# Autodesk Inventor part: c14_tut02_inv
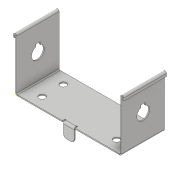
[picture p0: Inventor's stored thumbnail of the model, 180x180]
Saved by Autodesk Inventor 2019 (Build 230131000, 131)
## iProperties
Created: 2015-06
Part Number: c14_tut02_inv
Material: Generic
Document SubType Name: Sheet Metal
Designer: Sandeep
Density: 1 g/cm^3
Sheet Metal Rule: Default_mm
Appearance: Default
Flat Pattern Width: 5.12619 cm
Flat Pattern Length: 20.443 cm
Flat Pattern Area: 104.795 cm^2
Sheet Metal Width: 51.262 mm
Sheet Metal Length: 204.430 mm
Sheet Metal Area: 10479.484 mm^2
Author: Sandeep
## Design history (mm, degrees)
sketch "Sketch1"
  geometry: 1 further point
node "Face1"
  sketch "Sketch2"
    geometry: L1 (0, 0)-(100, 0); L2 (100, 0)-(100, 40); L3 (100, 40)-(0, 40); L4 (0, 40)-(0, 0)
    constraints: 8 end point, 2 parallel, 1 horizontal, 1 perpendicular
    dimensions: "d0" = 100 distance between parallel lines of L2 L4; "d1" = 40 distance between parallel lines of L1 L3
hole "Hole1" diameter "d5" = 6; stored, may be unused: countersink angle "d9" = 90 deg, drill point angle "d11" = 118 deg; dims "d3" = 10, "d4" = 15, "d6" = 6, "d7" = 4, "d8" = 2, "d10" = 1 (= Thickness)
pattern_linear "Rectangular Pattern1" dims "d14" = 20
pattern_linear "Rectangular Pattern2" dims "d17" = 70
node "Flange1"
node "Flange2"
feature "Hem1" dims "d38" = 1 (= BendReliefWidth), "d39" = 0.5 (= BendReliefDepth), "d40" = 2 (= MinimumRemnant), "d41" = 1 (= BendRadius), "d42" = 4 (= 4 x Thickness), "d43" = 1 (= Thickness), "d44" = 0.5 (= 0.5 x d43), "d82" = 1 (= Thickness), "SeamGap" = 0.01
feature "Hem2" dims "d45" = 1 (= BendReliefWidth), "d46" = 0.5 (= BendReliefDepth), "d47" = 2 (= MinimumRemnant), "d48" = 1 (= BendRadius), "d49" = 4 (= 4 x Thickness), "d50" = 1 (= Thickness), "d51" = 0.5 (= 0.5 x d50), "d82" = 1 (= Thickness), "SeamGap" = 0.01
sketch "Sketch7"
  geometry: L1 (0, 40)-(0, 0) reference; L2 (48, 0)-(0, 0) reference; 2 further points
  dimensions: "d52" = 25 distance from line of point (25, 20) L1; "d53" = 20 distance from line of L2 point (25, 20)
feature "iFeature15:1" sketch "Sketch7"
sketch "Sketch8"
  geometry: L1 (17.2, 18)-(17.2, 22) reference; L2 (19.343, 18)-(17.2, 18) reference; L3 (17.2, 22)-(19.343, 22) reference; L4 (17.2, 18)-(17.2, 22) reference; L5 (17.2, 22)-(19.343, 22) reference; L6 (19.343, 18)-(17.2, 18) reference; L7 (48, 0)-(48, 40) reference; L8 (48, 40)-(1.5, 40) reference; L9 (48, 0)-(1.5, 0) reference; L10 (1.5, 40)-(1.5, 0) reference; A1 r 6 centre (25, 20) between (19.343, 18) and (19.343, 22) reference; A2 r 6 centre (25, 20) between (19.343, 18) and (19.343, 22) reference; 1 further point
  node "Projected Loop1"
node "Flange3"
feature "Corner Round1" dims "d78" = 3
workplane "Work Plane1"
mirror "Mirror1"
body "Solid1"
face "Plate1" dims "d82" = 1 (= Thickness)
sketch "Sketch3"
  geometry: L1 through (20, 0) direction (-1, 0); L2 through (0, -25) direction (0, -1); L3 (0, -50)-(40, -50); L4 (40, -50)-(40, 0)
  constraints: 6 end point, 1 horizontal, 1 perpendicular, 1 vertical
face "Plate2" dims "d18" = 1 (= BendReliefWidth), "d19" = 0.5 (= BendReliefDepth), "d20" = 2 (= MinimumRemnant), "d21" = 1 (= BendRadius), "d22" = 50, "d23" = 90 deg, "d24" = 1 (= BendRadius), "d25" = 4 (= CornerReliefSize), "d26" = 1 (= GapSize), "d27" = 1 (= JacobiRadiusSize), "d82" = 1 (= Thickness), "SeamGap" = 0.01
bend "Bend1" dims "d18" = 1 (= BendReliefWidth), "d19" = 0.5 (= BendReliefDepth), "d20" = 2 (= MinimumRemnant), "d21" = 1 (= BendRadius), "d22" = 50, "d23" = 90 deg, "d24" = 1 (= BendRadius), "d82" = 1 (= Thickness), "SeamGap" = 0.01
feature "Corner1" dims "d22" = 50, "d23" = 90 deg, "d25" = 4 (= CornerReliefSize), "d26" = 1 (= GapSize), "d27" = 1 (= JacobiRadiusSize)
sketch "Sketch4"
  geometry: L1 through (20, 0) direction (-1, 5.47e-48); L2 through (0, -25) direction (-2.71e-32, -1); L3 (0, -50)-(40, -50); L4 (40, -50)-(40, 0)
  constraints: 6 end point, 1 horizontal, 1 perpendicular, 1 vertical
face "Plate3" dims "d28" = 1 (= BendReliefWidth), "d29" = 0.5 (= BendReliefDepth), "d30" = 2 (= MinimumRemnant), "d31" = 1 (= BendRadius), "d32" = 50, "d33" = 90 deg, "d34" = 1 (= BendRadius), "d35" = 4 (= CornerReliefSize), "d36" = 1 (= GapSize), "d37" = 1 (= JacobiRadiusSize), "d82" = 1 (= Thickness), "SeamGap" = 0.01
bend "Bend2" dims "d28" = 1 (= BendReliefWidth), "d29" = 0.5 (= BendReliefDepth), "d30" = 2 (= MinimumRemnant), "d31" = 1 (= BendRadius), "d32" = 50, "d33" = 90 deg, "d34" = 1 (= BendRadius), "d82" = 1 (= Thickness), "SeamGap" = 0.01
feature "Corner2" dims "d32" = 50, "d33" = 90 deg, "d35" = 4 (= CornerReliefSize), "d36" = 1 (= GapSize), "d37" = 1 (= JacobiRadiusSize)
sketch "Sketch9"
  geometry: L1 (-53, 0)-(-43, 0); L2 (-43, 0)-(-43, 13); L3 (-43, 13)-(-53, 13); L4 (-53, 13)-(-53, 0)
  constraints: 8 end point
face "Plate4" dims "d67" = 1 (= BendReliefWidth), "d68" = 0.5 (= BendReliefDepth), "d69" = 2 (= MinimumRemnant), "d70" = 1 (= BendRadius), "d71" = 10, "d72" = 13, "d73" = 90 deg, "d74" = 1 (= BendRadius), "d75" = 4 (= CornerReliefSize), "d76" = 1 (= GapSize), "d77" = 1 (= JacobiRadiusSize), "d82" = 1 (= Thickness), "SeamGap" = 0.01
bend "Bend3" dims "d67" = 1 (= BendReliefWidth), "d68" = 0.5 (= BendReliefDepth), "d69" = 2 (= MinimumRemnant), "d70" = 1 (= BendRadius), "d72" = 13, "d73" = 90 deg, "d74" = 1 (= BendRadius), "d82" = 1 (= Thickness), "SeamGap" = 0.01
feature "Corner3" dims "d72" = 13, "d73" = 90 deg, "d75" = 4 (= CornerReliefSize), "d76" = 1 (= GapSize), "d77" = 1 (= JacobiRadiusSize)
sketch "Sketch5"
  geometry: L1 (1, 0)-(0, 0); L2 (-1, 0)-(-1, -2.5); L3 (-1, -2.5)-(-2, -2.5); L4 (-2, -2.5)-(-2, 0); A1 r 0.5 centre (-0.5, 0) between (0, 0) and (-1, 0); A2 r 1.5 centre (-0.5, 0) between (1, 0) and (-2, 0); 2 further points
  constraints: 8 end point, 4 point on circle
sketch "Sketch6"
  geometry: L1 (0, 0)-(1, 0); L2 (2, 0)-(2, -2.5); L3 (2, -2.5)-(3, -2.5); L4 (3, -2.5)-(3, 0); A1 r 0.5 centre (1.5, 0) between (2, 0) and (1, 0); A2 r 1.5 centre (1.5, 0) between (3, 0) and (0, 0); 2 further points
  constraints: 8 end point, 4 point on circle
feature "Definition1"
other parameters: "Thickness" = 1 (derived), "BendRadius" = 1 (= Thickness), "BendReliefWidth" = 1 (= Thickness), "BendReliefDepth" = 0.5 (= 0.5 x Thickness), "CornerReliefSize" = 4 (= 4 x Thickness), "MinimumRemnant" = 2 (= 2 x Thickness), "TransitionRadius" = 1 (= BendRadius), "JacobiRadiusSize" = 1 (= BendRadius), "GapSize" = 1 (= Thickness), "d2" = 1 (= BendRadius), "d83" = 90 deg, "BendRadius" = 1, "BendReliefDepth" = 0.5, "BendReliefWidth" = 1, "CornerReliefSize" = 4, "GapSize" = 1, "JacobiRadiusSize" = 1, "MinimumRemnant" = 2, "Thickness" = 1, "TransitionRadius" = 1
